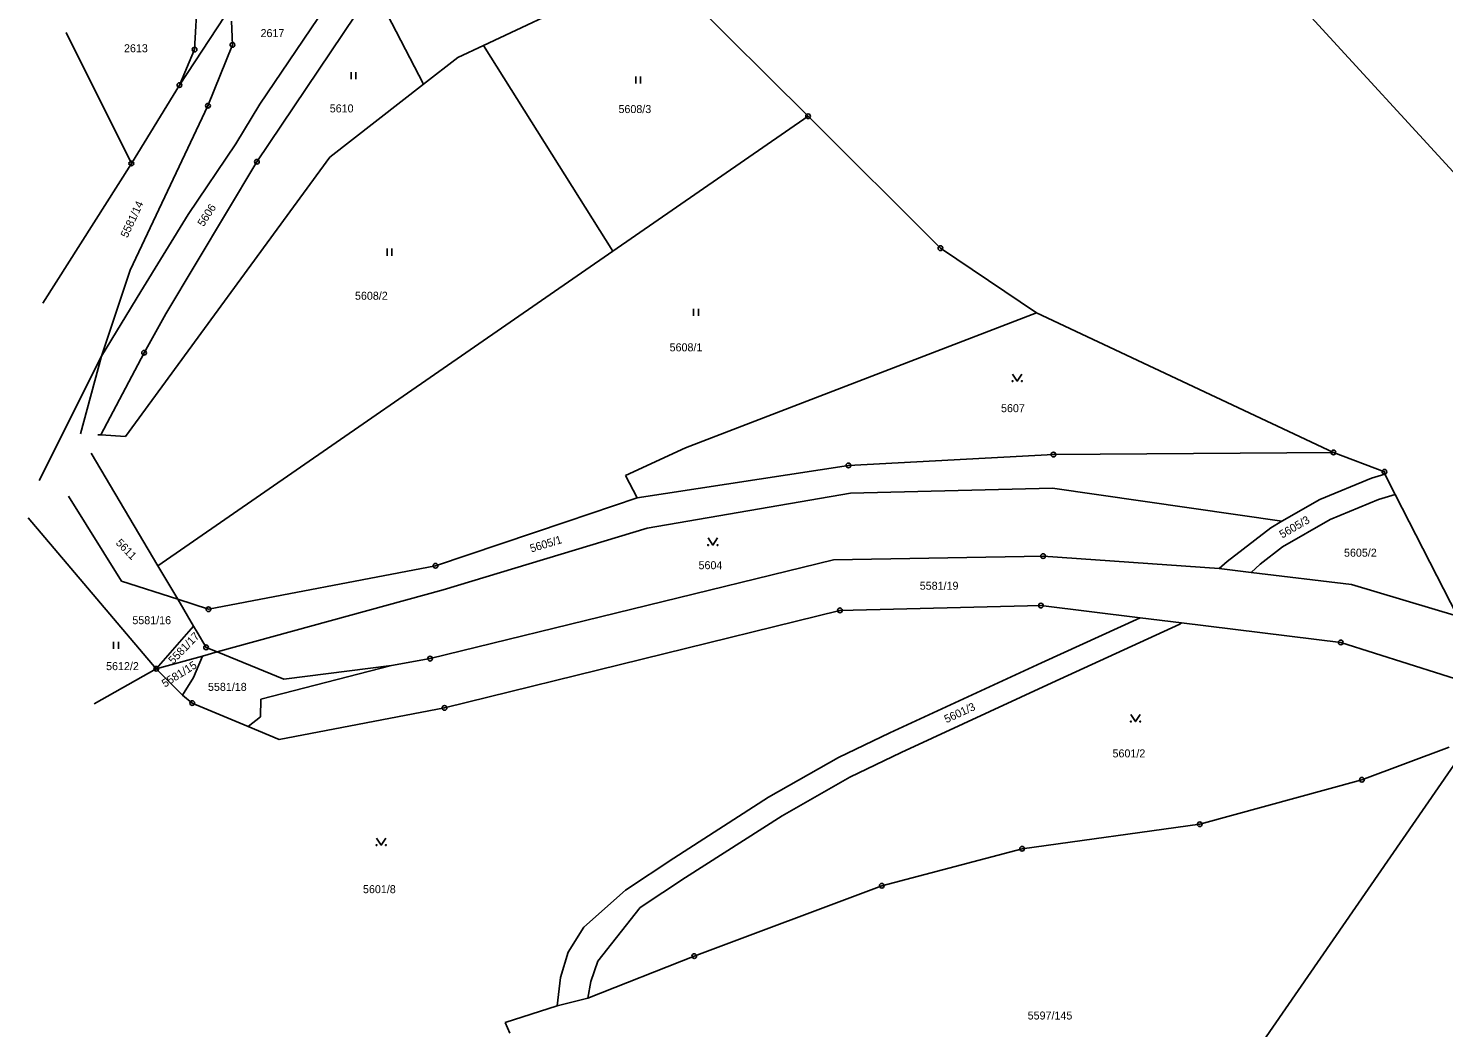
# Model space of a CAD drawing. Extents: x -639466 to -639004, y -1138878 to -1138229.
# Drawn here: x -639447.6 to -639297.3, y -1138704.8 to -1138598.7 of the extents above; entities that cross this region are included whole.
import ezdxf

# ---------------------------------------------------------------- set-up
doc = ezdxf.new("R2010")
doc.units = 0
for name, color, linetype in [('Hranice parcel', 7, 'Continuous'), ('Parcelní čísla', 7, 'Continuous'), ('Značky bodu BP', 7, 'Continuous'), ('Značky kultur', 7, 'Continuous')]:
    doc.layers.add(name, color=color, linetype=linetype)

msp = doc.modelspace()

# ---------------------------------------------------------------- linework, layer by layer
at = {"layer": 'Hranice parcel'}
for p, q in [((-639423.03, -1138606.71), (-639413.26, -1138592.31)), ((-639381.02, -1138591.87), (-639399.28, -1138600.51)), ((-639364.8, -1138608.01), (-639381.02, -1138591.87)), ((-639284.48, -1138626.82), (-639315.73, -1138592.73)), ((-639429.95, -1138600.92), (-639429.65, -1138595.12)), ((-639423.34, -1138612.84), (-639410.93, -1138594.36)), ((-639410.93, -1138594.36), (-639405.65, -1138604.6)), ((-639431.56, -1138604.7), (-639426.75, -1138597.38)), ((-639426.03, -1138597.92), (-639425.93, -1138600.43)), ((-639443.6, -1138599.1), (-639436.67, -1138613.02)), ((-639431.56, -1138604.7), (-639429.95, -1138600.92)), ((-639425.93, -1138600.43), (-639428.53, -1138606.89)), ((-639402.01, -1138601.76), (-639405.65, -1138604.6)), ((-639399.28, -1138600.51), (-639402.01, -1138601.76)), ((-639385.55, -1138622.34), (-639399.28, -1138600.51)), ((-639436.67, -1138613.02), (-639431.56, -1138604.7)), ((-639405.65, -1138604.6), (-639415.6, -1138612.36)), ((-639428.53, -1138606.89), (-639436.78, -1138624.37)), ((-639425.56, -1138610.94), (-639423.03, -1138606.71)), ((-639364.8, -1138608.01), (-639385.55, -1138622.34)), ((-639350.75, -1138622.02), (-639364.8, -1138608.01)), ((-639415.6, -1138612.36), (-639437.3, -1138642.04)), ((-639430.64, -1138618.46), (-639425.56, -1138610.94)), ((-639446.07, -1138627.87), (-639436.67, -1138613.02)), ((-639433.02, -1138628.98), (-639423.34, -1138612.84)), ((-639435.66, -1138626.61), (-639430.64, -1138618.46)), ((-639385.55, -1138622.34), (-639433.86, -1138655.76)), ((-639340.57, -1138628.9), (-639350.75, -1138622.02)), ((-639436.78, -1138624.37), (-639439.84, -1138633.5)), ((-639439.84, -1138633.5), (-639435.66, -1138626.61)), ((-639340.57, -1138628.9), (-639377.83, -1138643.22)), ((-639309.02, -1138643.71), (-639340.57, -1138628.9)), ((-639435.32, -1138633.13), (-639433.02, -1138628.98)), ((-639439.92, -1138641.85), (-639435.32, -1138633.13)), ((-639446.46, -1138646.7), (-639439.84, -1138633.5)), ((-639439.84, -1138633.5), (-639442.08, -1138641.73)), ((-639440.21, -1138641.84), (-639439.92, -1138641.85)), ((-639437.3, -1138642.04), (-639439.92, -1138641.85)), ((-639440.94, -1138643.8), (-639433.86, -1138655.76)), ((-639377.83, -1138643.22), (-639384.18, -1138646.18)), ((-639309.02, -1138643.71), (-639338.75, -1138643.95)), ((-639303.61, -1138645.77), (-639309.02, -1138643.71)), ((-639360.53, -1138645.1), (-639382.96, -1138648.55)), ((-639338.75, -1138643.95), (-639360.53, -1138645.1)), ((-639384.18, -1138646.18), (-639382.96, -1138648.55)), ((-639310.46, -1138648.71), (-639304.99, -1138646.44)), ((-639304.99, -1138646.44), (-639303.57, -1138646.01)), ((-639303.57, -1138646.01), (-639303.61, -1138645.77)), ((-639302.47, -1138648.17), (-639303.57, -1138646.01)), ((-639437.7, -1138657.39), (-639443.35, -1138648.37)), ((-639360.29, -1138648.04), (-639381.9, -1138651.77)), ((-639338.84, -1138647.52), (-639360.29, -1138648.04)), ((-639314.49, -1138651.03), (-639338.84, -1138647.52)), ((-639302.47, -1138648.17), (-639304.22, -1138648.7)), ((-639295.86, -1138661.12), (-639302.47, -1138648.17)), ((-639382.96, -1138648.55), (-639390.48, -1138651.08)), ((-639314.49, -1138651.03), (-639310.46, -1138648.71)), ((-639304.22, -1138648.7), (-639309.38, -1138650.85)), ((-639434.02, -1138666.69), (-639447.61, -1138650.68)), ((-639390.48, -1138651.08), (-639404.37, -1138655.76)), ((-639315.68, -1138651.72), (-639314.49, -1138651.03)), ((-639309.38, -1138650.85), (-639314.42, -1138653.76)), ((-639381.9, -1138651.77), (-639403.54, -1138658.31)), ((-639320.3, -1138655.31), (-639315.68, -1138651.72)), ((-639314.42, -1138653.76), (-639316.8, -1138655.57)), ((-639433.86, -1138655.76), (-639431.75, -1138659.31)), ((-639404.37, -1138655.76), (-639428.49, -1138660.37)), ((-639404.95, -1138665.62), (-639362.1, -1138655.14)), ((-639362.1, -1138655.14), (-639339.85, -1138654.73)), ((-639339.85, -1138654.73), (-639321.17, -1138656.05)), ((-639321.17, -1138656.05), (-639320.3, -1138655.31)), ((-639316.8, -1138655.57), (-639317.75, -1138656.46)), ((-639431.75, -1138659.31), (-639437.7, -1138657.39)), ((-639321.17, -1138656.05), (-639317.75, -1138656.46)), ((-639317.75, -1138656.46), (-639307.09, -1138657.75)), ((-639403.54, -1138658.31), (-639427.54, -1138664.91)), ((-639307.09, -1138657.75), (-639295.86, -1138661.12)), ((-639431.75, -1138659.31), (-639430.06, -1138662.17)), ((-639428.49, -1138660.37), (-639431.75, -1138659.31)), ((-639340.09, -1138659.99), (-639361.42, -1138660.49)), ((-639329.53, -1138661.29), (-639340.09, -1138659.99)), ((-639361.42, -1138660.49), (-639403.41, -1138670.85)), ((-639329.53, -1138661.29), (-639340.02, -1138666.06)), ((-639325.33, -1138661.97), (-639338.93, -1138668.18)), ((-639325.14, -1138661.83), (-639329.53, -1138661.29)), ((-639325.14, -1138661.83), (-639325.33, -1138661.97)), ((-639308.24, -1138663.9), (-639325.14, -1138661.83)), ((-639434.02, -1138666.69), (-639430.8, -1138663.01)), ((-639430.8, -1138663.01), (-639430.06, -1138662.17)), ((-639430.06, -1138662.17), (-639429.68, -1138662.82)), ((-639429.68, -1138662.82), (-639428.73, -1138664.42)), ((-639429.11, -1138665.34), (-639427.54, -1138664.91)), ((-639428.73, -1138664.42), (-639427.54, -1138664.91)), ((-639427.54, -1138664.91), (-639420.49, -1138667.8)), ((-639291.85, -1138669.1), (-639308.24, -1138663.9)), ((-639429.11, -1138665.34), (-639434.02, -1138666.69)), ((-639430.06, -1138667.64), (-639429.11, -1138665.34)), ((-639422.92, -1138669.91), (-639409.03, -1138666.34)), ((-639420.49, -1138667.8), (-639409.03, -1138666.34)), ((-639409.03, -1138666.34), (-639404.95, -1138665.62)), ((-639340.02, -1138666.06), (-639356.11, -1138673.51)), ((-639440.61, -1138670.43), (-639434.02, -1138666.69)), ((-639431.24, -1138669.5), (-639434.02, -1138666.69)), ((-639431.24, -1138669.5), (-639430.06, -1138667.64)), ((-639338.93, -1138668.18), (-639354.93, -1138675.6)), ((-639430.2, -1138670.34), (-639431.24, -1138669.5)), ((-639424.27, -1138672.83), (-639430.2, -1138670.34)), ((-639422.97, -1138671.8), (-639422.92, -1138669.91)), ((-639403.41, -1138670.85), (-639420.97, -1138674.21)), ((-639424.27, -1138672.83), (-639422.97, -1138671.8)), ((-639420.97, -1138674.21), (-639424.27, -1138672.83)), ((-639356.11, -1138673.51), (-639361.59, -1138676.13)), ((-639294.17, -1138673.97), (-639319.77, -1138710.96)), ((-639296.73, -1138675.01), (-639306, -1138678.49)), ((-639361.59, -1138676.13), (-639369.01, -1138680.32)), ((-639354.93, -1138675.6), (-639360.37, -1138678.21)), ((-639360.37, -1138678.21), (-639367.57, -1138682.33)), ((-639306, -1138678.49), (-639323.22, -1138683.21)), ((-639369.01, -1138680.32), (-639379.07, -1138686.82)), ((-639367.57, -1138682.33), (-639377.82, -1138688.86)), ((-639323.22, -1138683.21), (-639342.09, -1138685.81)), ((-639342.09, -1138685.81), (-639356.98, -1138689.74)), ((-639379.07, -1138686.82), (-639384.18, -1138690.22)), ((-639377.82, -1138688.86), (-639382.65, -1138692.04)), ((-639384.18, -1138690.22), (-639388.63, -1138694.13)), ((-639356.98, -1138689.74), (-639376.89, -1138697.22)), ((-639382.65, -1138692.04), (-639387.13, -1138697.77)), ((-639388.63, -1138694.13), (-639390.29, -1138696.78)), ((-639390.29, -1138696.78), (-639391.11, -1138699.49)), ((-639376.89, -1138697.22), (-639388.2, -1138701.67)), ((-639387.13, -1138697.77), (-639387.89, -1138699.91)), ((-639391.11, -1138699.49), (-639391.46, -1138702.48)), ((-639387.89, -1138699.91), (-639388.2, -1138701.67)), ((-639391.46, -1138702.48), (-639396.96, -1138704.25)), ((-639388.2, -1138701.67), (-639391.46, -1138702.48)), ((-639396.96, -1138704.25), (-639396.48, -1138705.39))]:
    msp.add_line(p, q, dxfattribs=at)
at = {"layer": 'Značky bodu BP'}
for centre, radius in [((-639425.93, -1138600.43), 0.25), ((-639429.95, -1138600.92), 0.25), ((-639429.95, -1138600.92), 0.0152), ((-639425.93, -1138600.43), 0.0152), ((-639431.56, -1138604.7), 0.25), ((-639431.56, -1138604.7), 0.0152), ((-639428.53, -1138606.89), 0.25), ((-639428.53, -1138606.89), 0.0152), ((-639364.8, -1138608.01), 0.25), ((-639364.8, -1138608.01), 0.0152), ((-639436.67, -1138613.02), 0.25), ((-639436.67, -1138613.02), 0.0152), ((-639423.34, -1138612.84), 0.25), ((-639423.34, -1138612.84), 0.0152), ((-639350.75, -1138622.02), 0.25), ((-639350.75, -1138622.02), 0.0152), ((-639435.32, -1138633.13), 0.25), ((-639435.32, -1138633.13), 0.0152), ((-639338.75, -1138643.95), 0.25), ((-639338.75, -1138643.95), 0.0152), ((-639309.02, -1138643.71), 0.25), ((-639309.02, -1138643.71), 0.0152), ((-639360.53, -1138645.1), 0.25), ((-639360.53, -1138645.1), 0.0152), ((-639303.61, -1138645.77), 0.25), ((-639303.61, -1138645.77), 0.0152), ((-639404.37, -1138655.76), 0.25), ((-639404.37, -1138655.76), 0.0152), ((-639339.85, -1138654.73), 0.25), ((-639339.85, -1138654.73), 0.0152), ((-639428.49, -1138660.37), 0.25), ((-639428.49, -1138660.37), 0.0152), ((-639361.42, -1138660.49), 0.25), ((-639340.09, -1138659.99), 0.25), ((-639340.09, -1138659.99), 0.0152), ((-639361.42, -1138660.49), 0.0152), ((-639428.73, -1138664.42), 0.25), ((-639428.73, -1138664.42), 0.0152), ((-639308.24, -1138663.9), 0.25), ((-639308.24, -1138663.9), 0.0152), ((-639434.02, -1138666.69), 0.25), ((-639404.95, -1138665.62), 0.25), ((-639404.95, -1138665.62), 0.0152), ((-639434.02, -1138666.69), 0.0152), ((-639430.2, -1138670.34), 0.25), ((-639430.2, -1138670.34), 0.0152), ((-639403.41, -1138670.85), 0.25), ((-639403.41, -1138670.85), 0.0152), ((-639306, -1138678.49), 0.25), ((-639306, -1138678.49), 0.0152), ((-639323.22, -1138683.21), 0.25), ((-639323.22, -1138683.21), 0.0152), ((-639342.09, -1138685.81), 0.25), ((-639342.09, -1138685.81), 0.0152), ((-639356.98, -1138689.74), 0.25), ((-639356.98, -1138689.74), 0.0152), ((-639376.89, -1138697.22), 0.25), ((-639376.89, -1138697.22), 0.0152)]:
    msp.add_circle(centre, radius, dxfattribs=at)
at = {"layer": 'Značky kultur'}
for p, q in [((-639413.33, -1138604.06), (-639413.33, -1138603.31)), ((-639412.83, -1138604.06), (-639412.83, -1138603.31)), ((-639383.1, -1138604.52), (-639383.1, -1138603.77)), ((-639382.6, -1138604.52), (-639382.6, -1138603.77)), ((-639409.51, -1138622.82), (-639409.51, -1138622.07)), ((-639409.01, -1138622.82), (-639409.01, -1138622.07)), ((-639376.97, -1138629.2), (-639376.97, -1138628.45)), ((-639376.46, -1138629.2), (-639376.46, -1138628.45)), ((-639438.55, -1138664.59), (-639438.55, -1138663.84)), ((-639438.05, -1138664.59), (-639438.05, -1138663.84))]:
    msp.add_line(p, q, dxfattribs=at)
for points in [[(-639343.1, -1138635.39), (-639342.6, -1138636.14), (-639342.1, -1138635.39)], [(-639375.42, -1138652.8), (-639374.92, -1138653.55), (-639374.42, -1138652.8)], [(-639330.53, -1138671.55), (-639330.03, -1138672.3), (-639329.53, -1138671.55)], [(-639410.63, -1138684.68), (-639410.13, -1138685.43), (-639409.63, -1138684.68)]]:
    msp.add_lwpolyline(points, dxfattribs=at)
for centre in [(-639343.1, -1138636.14), (-639342.1, -1138636.14), (-639375.42, -1138653.55), (-639374.42, -1138653.55), (-639330.53, -1138672.3), (-639329.53, -1138672.3), (-639410.63, -1138685.43), (-639409.63, -1138685.43)]:
    msp.add_circle(centre, 0.05, dxfattribs=at)

# ---------------------------------------------------------------- texts
at = {"layer": 'Parcelní čísla'}
for s, p in [('2617', (-639422.95, -1138599.6)), ('2613', (-639437.45, -1138601.21)), ('5610', (-639415.6, -1138607.6)), ('5608/3', (-639384.94, -1138607.67)), ('5608/2', (-639412.92, -1138627.5)), ('5608/1', (-639379.51, -1138632.98)), ('5607', (-639344.32, -1138639.44)), ('5605/2', (-639307.9, -1138654.79)), ('5604', (-639376.44, -1138656.12)), ('5581/19', (-639352.95, -1138658.3)), ('5581/16', (-639436.56, -1138661.96)), ('5612/2', (-639439.35, -1138666.84)), ('5581/18', (-639428.53, -1138669.04)), ('5601/2', (-639332.48, -1138676.11)), ('5601/8', (-639412.07, -1138690.53)), ('5597/145', (-639341.49, -1138703.95))]:
    msp.add_text(s, height=0.85, dxfattribs=at).set_placement(p)
for s, rotation, p in [('5581/14', 65, (-639437.09, -1138620.99)), ('5606', 57, (-639429, -1138619.8)), ('5605/3', 30, (-639314.46, -1138652.87)), ('5611', 314, (-639438.38, -1138653.39)), ('5605/1', 17, (-639394.2, -1138654.35)), ('5581/17', 46, (-639432.22, -1138666.26)), ('5581/15', 32, (-639433.11, -1138668.71)), ('5601/3', 25, (-639350.11, -1138672.49))]:
    msp.add_text(s, height=0.85, rotation=rotation, dxfattribs=at).set_placement(p)

doc.saveas('drawing.dxf')
